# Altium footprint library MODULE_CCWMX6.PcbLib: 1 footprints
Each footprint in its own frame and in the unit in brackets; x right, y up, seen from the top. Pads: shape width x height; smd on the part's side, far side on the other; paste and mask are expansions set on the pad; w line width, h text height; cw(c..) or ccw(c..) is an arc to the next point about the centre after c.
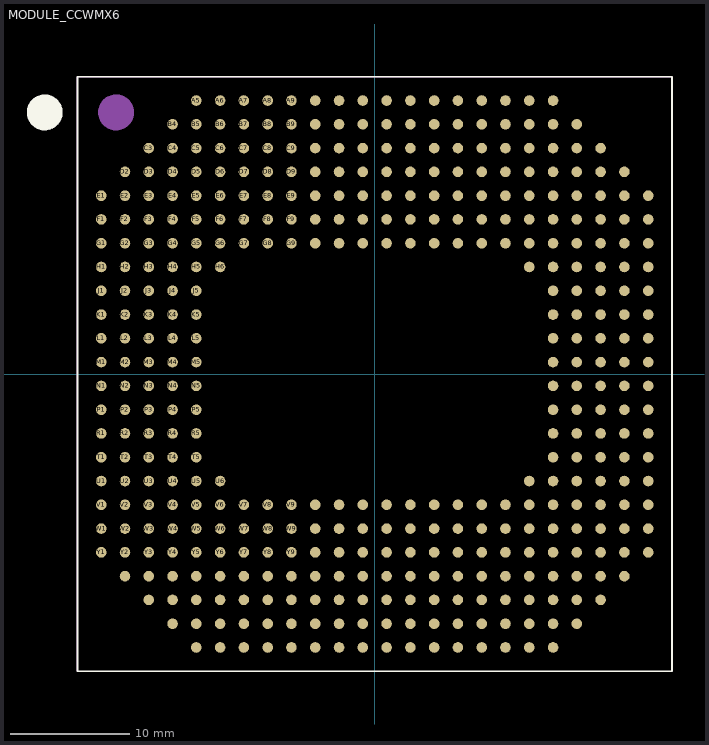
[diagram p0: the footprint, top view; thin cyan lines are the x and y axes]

## MODULE_CCWMX6 [mil]
height 220.47
pads (400):
  round 35 smd: A5(-590.55,905.51) A6(-511.81,905.51) A7(-433.07,905.51) A8(-354.33,905.51) A9(-275.59,905.51) A10(-196.85,905.51) A11(-118.11,905.51) A12(-39.37,905.51) A13(39.37,905.51) A14(118.11,905.51) A15(196.85,905.51) A16(275.59,905.51) A17(354.33,905.51) A18(433.07,905.51) A19(511.81,905.51) A20(590.55,905.51) AA2(-826.77,-669.29) AA3(-748.03,-669.29) AA4(-669.29,-669.29) AA5(-590.55,-669.29) AA6(-511.81,-669.29) AA7(-433.07,-669.29) AA8(-354.33,-669.29) AA9(-275.59,-669.29) AA10(-196.85,-669.29) AA11(-118.11,-669.29) AA12(-39.37,-669.29) AA13(39.37,-669.29) AA14(118.11,-669.29) AA15(196.85,-669.29) AA16(275.59,-669.29) AA17(354.33,-669.29) AA18(433.07,-669.29) AA19(511.81,-669.29) AA20(590.55,-669.29) AA21(669.29,-669.29) AA22(748.03,-669.29) AA23(826.77,-669.29) AB3(-748.03,-748.03) AB4(-669.29,-748.03) AB5(-590.55,-748.03) AB6(-511.81,-748.03) AB7(-433.07,-748.03) AB8(-354.33,-748.03) AB9(-275.59,-748.03) AB10(-196.85,-748.03) AB11(-118.11,-748.03) AB12(-39.37,-748.03) AB13(39.37,-748.03) AB14(118.11,-748.03) AB15(196.85,-748.03) AB16(275.59,-748.03) AB17(354.33,-748.03) AB18(433.07,-748.03) AB19(511.81,-748.03) AB20(590.55,-748.03) AB21(669.29,-748.03) AB22(748.03,-748.03) AC4(-669.29,-826.77) AC5(-590.55,-826.77) AC6(-511.81,-826.77) AC7(-433.07,-826.77) AC8(-354.33,-826.77) AC9(-275.59,-826.77) AC10(-196.85,-826.77) AC11(-118.11,-826.77) AC12(-39.37,-826.77) AC13(39.37,-826.77) AC14(118.11,-826.77) AC15(196.85,-826.77) AC16(275.59,-826.77) AC17(354.33,-826.77) AC18(433.07,-826.77) AC19(511.81,-826.77) AC20(590.55,-826.77) AC21(669.29,-826.77) AD5(-590.55,-905.51) AD6(-511.81,-905.51) AD7(-433.07,-905.51) AD8(-354.33,-905.51) AD9(-275.59,-905.51) AD10(-196.85,-905.51) AD11(-118.11,-905.51) AD12(-39.37,-905.51) AD13(39.37,-905.51) AD14(118.11,-905.51) AD15(196.85,-905.51) AD16(275.59,-905.51) AD17(354.33,-905.51) AD18(433.07,-905.51) AD19(511.81,-905.51) AD20(590.55,-905.51) B4(-669.29,826.77) B5(-590.55,826.77) B6(-511.81,826.77) B7(-433.07,826.77) B8(-354.33,826.77) B9(-275.59,826.77) B10(-196.85,826.77) B11(-118.11,826.77) B12(-39.37,826.77) B13(39.37,826.77) B14(118.11,826.77) B15(196.85,826.77) B16(275.59,826.77) B17(354.33,826.77) B18(433.07,826.77) B19(511.81,826.77) B20(590.55,826.77) B21(669.29,826.77) C3(-748.03,748.03) C4(-669.29,748.03) C5(-590.55,748.03) C6(-511.81,748.03) C7(-433.07,748.03) C8(-354.33,748.03) C9(-275.59,748.03) C10(-196.85,748.03) C11(-118.11,748.03) C12(-39.37,748.03) C13(39.37,748.03) C14(118.11,748.03) C15(196.85,748.03) C16(275.59,748.03) C17(354.33,748.03) C18(433.07,748.03) C19(511.81,748.03) C20(590.55,748.03) C21(669.29,748.03) C22(748.03,748.03) D2(-826.77,669.29) D3(-748.03,669.29) D4(-669.29,669.29) D5(-590.55,669.29) D6(-511.81,669.29) D7(-433.07,669.29) D8(-354.33,669.29) D9(-275.59,669.29) D10(-196.85,669.29) D11(-118.11,669.29) D12(-39.37,669.29) D13(39.37,669.29) D14(118.11,669.29) D15(196.85,669.29) D16(275.59,669.29) D17(354.33,669.29) D18(433.07,669.29) D19(511.81,669.29) D20(590.55,669.29) D21(669.29,669.29) D22(748.03,669.29) D23(826.77,669.29) E1(-905.51,590.55) E2(-826.77,590.55) E3(-748.03,590.55) E4(-669.29,590.55) E5(-590.55,590.55) E6(-511.81,590.55) E7(-433.07,590.55) E8(-354.33,590.55) E9(-275.59,590.55) E10(-196.85,590.55) E11(-118.11,590.55) E12(-39.37,590.55) E13(39.37,590.55) E14(118.11,590.55) E15(196.85,590.55) E16(275.59,590.55) E17(354.33,590.55) E18(433.07,590.55) E19(511.81,590.55) E20(590.55,590.55) E21(669.29,590.55) E22(748.03,590.55) E23(826.77,590.55) E24(905.51,590.55) F1(-905.51,511.81) F2(-826.77,511.81) F3(-748.03,511.81) F4(-669.29,511.81) F5(-590.55,511.81) F6(-511.81,511.81) F7(-433.07,511.81) F8(-354.33,511.81) F9(-275.59,511.81) F10(-196.85,511.81) F11(-118.11,511.81) F12(-39.37,511.81) F13(39.37,511.81) F14(118.11,511.81) F15(196.85,511.81) F16(275.59,511.81) F17(354.33,511.81) F18(433.07,511.81) F19(511.81,511.81) F20(590.55,511.81) F21(669.29,511.81) F22(748.03,511.81) F23(826.77,511.81) F24(905.51,511.81) G1(-905.51,433.07) G2(-826.77,433.07) G3(-748.03,433.07) G4(-669.29,433.07) G5(-590.55,433.07) G6(-511.81,433.07) G7(-433.07,433.07) G8(-354.33,433.07) G9(-275.59,433.07) G10(-196.85,433.07) G11(-118.11,433.07) G12(-39.37,433.07) G13(39.37,433.07) G14(118.11,433.07) G15(196.85,433.07) G16(275.59,433.07) G17(354.33,433.07) G18(433.07,433.07) G19(511.81,433.07) G20(590.55,433.07) G21(669.29,433.07) G22(748.03,433.07) G23(826.77,433.07) G24(905.51,433.07) H1(-905.51,354.33) H2(-826.77,354.33) H3(-748.03,354.33) H4(-669.29,354.33) H5(-590.55,354.33) H6(-511.81,354.33) H19(511.81,354.33) H20(590.55,354.33) H21(669.29,354.33) H22(748.03,354.33) H23(826.77,354.33) H24(905.51,354.33) J1(-905.51,275.59) J2(-826.77,275.59) J3(-748.03,275.59) J4(-669.29,275.59) J5(-590.55,275.59) J20(590.55,275.59) J21(669.29,275.59) J22(748.03,275.59) J23(826.77,275.59) J24(905.51,275.59) K1(-905.51,196.85) K2(-826.77,196.85) K3(-748.03,196.85) K4(-669.29,196.85) K5(-590.55,196.85) K20(590.55,196.85) K21(669.29,196.85) K22(748.03,196.85) K23(826.77,196.85) K24(905.51,196.85) L1(-905.51,118.11) L2(-826.77,118.11) L3(-748.03,118.11) L4(-669.29,118.11) L5(-590.55,118.11) L20(590.55,118.11) L21(669.29,118.11) L22(748.03,118.11) L23(826.77,118.11) L24(905.51,118.11) M1(-905.51,39.37) M2(-826.77,39.37) M3(-748.03,39.37) M4(-669.29,39.37) M5(-590.55,39.37) M20(590.55,39.37) M21(669.29,39.37) M22(748.03,39.37) M23(826.77,39.37) M24(905.51,39.37) N1(-905.51,-39.37) N2(-826.77,-39.37) N3(-748.03,-39.37) N4(-669.29,-39.37) N5(-590.55,-39.37) N20(590.55,-39.37) N21(669.29,-39.37) N22(748.03,-39.37) N23(826.77,-39.37) N24(905.51,-39.37) P1(-905.51,-118.11) P2(-826.77,-118.11) P3(-748.03,-118.11) P4(-669.29,-118.11) P5(-590.55,-118.11) P20(590.55,-118.11) P21(669.29,-118.11) P22(748.03,-118.11) P23(826.77,-118.11) P24(905.51,-118.11) R1(-905.51,-196.85) R2(-826.77,-196.85) R3(-748.03,-196.85) R4(-669.29,-196.85) R5(-590.55,-196.85) R20(590.55,-196.85) R21(669.29,-196.85) R22(748.03,-196.85) R23(826.77,-196.85) R24(905.51,-196.85) T1(-905.51,-275.59) T2(-826.77,-275.59) T3(-748.03,-275.59) T4(-669.29,-275.59) T5(-590.55,-275.59) T20(590.55,-275.59) T21(669.29,-275.59) T22(748.03,-275.59) T23(826.77,-275.59) T24(905.51,-275.59) U1(-905.51,-354.33) U2(-826.77,-354.33) U3(-748.03,-354.33) U4(-669.29,-354.33) U5(-590.55,-354.33) U6(-511.81,-354.33) U19(511.81,-354.33) U20(590.55,-354.33) U21(669.29,-354.33) U22(748.03,-354.33) U23(826.77,-354.33) U24(905.51,-354.33) V1(-905.51,-433.07) V2(-826.77,-433.07) V3(-748.03,-433.07) V4(-669.29,-433.07) V5(-590.55,-433.07) V6(-511.81,-433.07) V7(-433.07,-433.07) V8(-354.33,-433.07) V9(-275.59,-433.07) V10(-196.85,-433.07) V11(-118.11,-433.07) V12(-39.37,-433.07) V13(39.37,-433.07) V14(118.11,-433.07) V15(196.85,-433.07) V16(275.59,-433.07) V17(354.33,-433.07) V18(433.07,-433.07) V19(511.81,-433.07) V20(590.55,-433.07) V21(669.29,-433.07) V22(748.03,-433.07) V23(826.77,-433.07) V24(905.51,-433.07) W1(-905.51,-511.81) W2(-826.77,-511.81) W3(-748.03,-511.81) W4(-669.29,-511.81) W5(-590.55,-511.81) W6(-511.81,-511.81) W7(-433.07,-511.81) W8(-354.33,-511.81) W9(-275.59,-511.81) W10(-196.85,-511.81) W11(-118.11,-511.81) W12(-39.37,-511.81) W13(39.37,-511.81) W14(118.11,-511.81) W15(196.85,-511.81) W16(275.59,-511.81) W17(354.33,-511.81) W18(433.07,-511.81) W19(511.81,-511.81) W20(590.55,-511.81) W21(669.29,-511.81) W22(748.03,-511.81) W23(826.77,-511.81) W24(905.51,-511.81) Y1(-905.51,-590.55) Y2(-826.77,-590.55) Y3(-748.03,-590.55) Y4(-669.29,-590.55) Y5(-590.55,-590.55) Y6(-511.81,-590.55) Y7(-433.07,-590.55) Y8(-354.33,-590.55) Y9(-275.59,-590.55) Y10(-196.85,-590.55) Y11(-118.11,-590.55) Y12(-39.37,-590.55) Y13(39.37,-590.55) Y14(118.11,-590.55) Y15(196.85,-590.55) Y16(275.59,-590.55) Y17(354.33,-590.55) Y18(433.07,-590.55) Y19(511.81,-590.55) Y20(590.55,-590.55) Y21(669.29,-590.55) Y22(748.03,-590.55) Y23(826.77,-590.55) Y24(905.51,-590.55)
Top Overlay:
  circle w60: c-1092.52,866.14 r29.53
  lines w6: -984.25,-984.25 984.25,-984.25 984.25,984.25 -984.25,984.25 -984.25,-984.25
Mechanical 3:
  circle w60: c-856.3,866.14 r29.53
  lines w4: -985,-985 -985,985 985,985 985,-985 -985,-985
  text ".Designator" at -90,-40 h80
3D body: height 39.41, standoff 39.37, extent -913.9,809.18 -796.25,927.05
3D body: height 220.47, standoff 0, extent -984.25,-984.25 984.25,984.25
